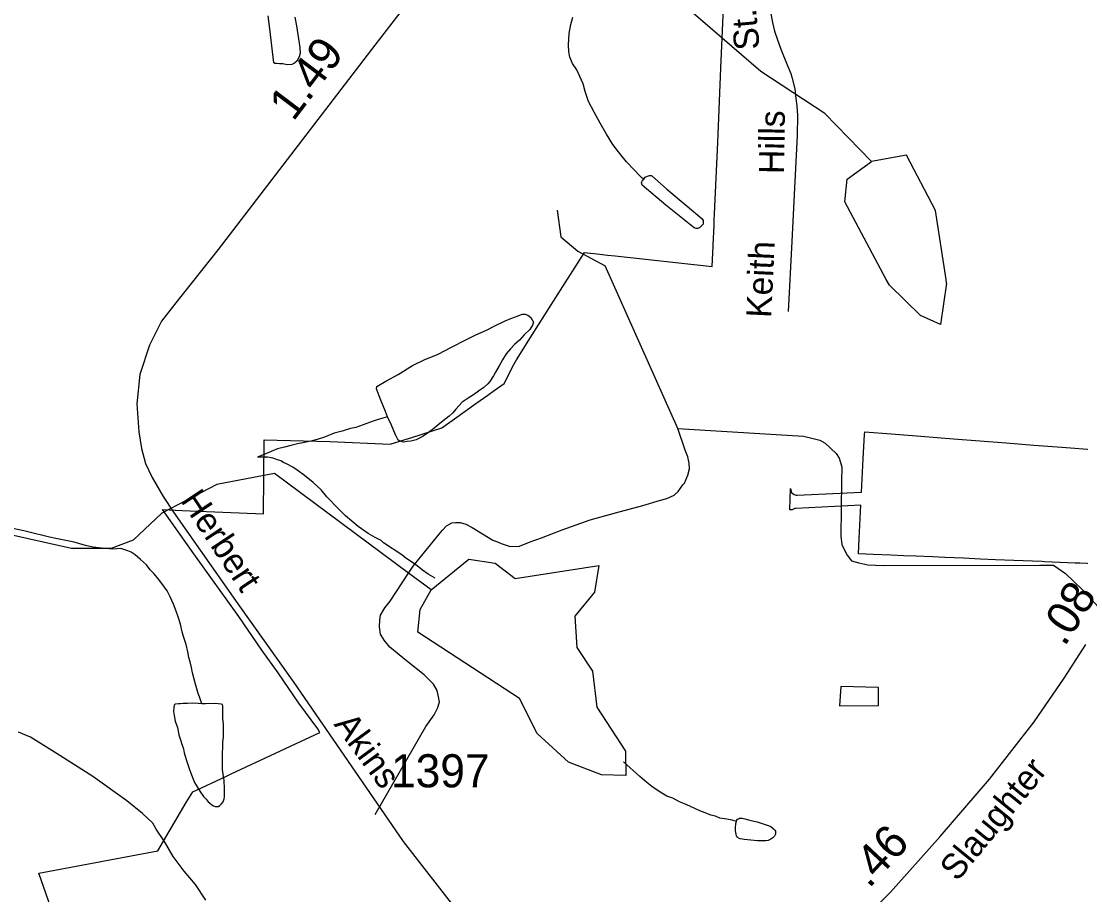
# Model space of a CAD drawing. Extents: x 2001466 to 2224147, y 644118 to 847247.
# Drawn here: x 2058287 to 2062288, y 680203 to 683500 of the extents above; entities that cross this region are included whole.
import ezdxf

# ---------------------------------------------------------------- set-up
doc = ezdxf.new("R2010")
doc.units = 0
for name, color, linetype in [('Exist Boundary Political City Limit New', 7, 'Continuous'), ('Exist Hydrographic Misc Water Feature', 7, 'Continuous'), ('Exist Road Non-System Type 51', 7, 'Continuous'), ('Exist Road Non-System Type 51 Label', 7, 'Continuous'), ('Exist Road Secondary Mileage Hundredths English Label', 7, 'Continuous'), ('Exist Road Secondary Type 51 Attributed', 7, 'Continuous'), ('Exist Road Secondary Type 51 Label', 7, 'Continuous'), ('Exist Road Secondary Type 51 Number Label', 7, 'Continuous'), ('Map Preparation Boundary City Limit Buffer Line', 7, 'Continuous')]:
    doc.layers.add(name, color=color, linetype=linetype)

msp = doc.modelspace()

# ---------------------------------------------------------------- linework, layer by layer
at = {"layer": 'Exist Boundary Political City Limit New'}
for points in [[(2058453.5, 680000), (2058353.2, 680284.1), (2058802.8, 680368.7), (2058909.6, 680551.6), (2058935.1, 680591.3), (2059059.1, 680650), (2059079.1, 680659.3), (2059414.8, 680815.9), (2059406.5, 680829.3), (2059335.6, 680926), (2059257.6, 681041), (2059195.1, 681126.8), (2059108.8, 681252.8), (2058938.4, 681490.1), (2058819.9, 681657), (2058894.9, 681653.8), (2059202, 681640.7), (2059204.4, 681919.9), (2059452.8, 681914.1), (2059679.9, 681903.6), (2059737.2, 681921.8), (2059761.2, 681929.3), (2059875.4, 681965.4), (2059922.6, 681999.1), (2060003.6, 682057), (2060048.4, 682088.9), (2060072.4, 682106.1), (2060110.1, 682133), (2060147.2, 682205.1), (2060156.4, 682222.8), (2060216.4, 682317.1), (2060288.2, 682430), (2060413.8, 682627), (2060471.5, 682620.6), (2060500.8, 682617.6), (2060530, 682614.4), (2060896, 682575.1), (2060899.2, 682651.2), (2060899.5, 682656.1), (2060902.8, 682729.5), (2060903.6, 682751), (2060904.6, 682772.7), (2060916.5, 683042.6), (2060928.9, 683323.6), (2060941.4, 683609.2)], [(2062423.1, 681448.3), (2062283.5, 681454.3), (2062266, 681455.1), (2062150.1, 681460), (2062139.9, 681460.4), (2062034.2, 681465), (2061965.6, 681467.9), (2061909.4, 681470.4), (2061845.2, 681473.2), (2061774.5, 681476.2), (2061728.8, 681478.2), (2061664.5, 681481), (2061618.9, 681482.9), (2061570.2, 681485.1), (2061503.9, 681488), (2061447.8, 681490.3), (2061450.8, 681548.2), (2061456, 681648.1), (2061457.2, 681673.1), (2061211.9, 681661), (2061208, 681660.5), (2061200.6, 681657.7), (2061197.4, 681655.4), (2061188.8, 681655.7), (2061191, 681737), (2061193.5, 681725), (2061195.6, 681721.5), (2061201.6, 681715.8), (2061205.1, 681713.7), (2061213, 681711.4), (2061217.1, 681711.3), (2061459.9, 681723.3), (2061461.1, 681748.1), (2061466.4, 681847.9), (2061471.2, 681940.3), (2061471.8, 681950.3), (2061571.5, 681942.5), (2061683.5, 681933.8), (2061806.5, 681924.2), (2061906.4, 681916.4), (2062006, 681908.7), (2062110.8, 681900.6), (2062215.4, 681892.5), (2062345, 681882.4)]]:
    msp.add_lwpolyline(points, dxfattribs=at)
at = {"layer": 'Exist Hydrographic Misc Water Feature'}
for p, q in [((2061564.7, 682503.5), (2061553.2, 682525.1)), ((2061780.7, 682512.2), (2061757.7, 682355.2)), ((2061780.7, 682512.2), (2061778.6, 682525.6)), ((2059834.7, 681354.2), (2059749.7, 681417.2))]:
    msp.add_line(p, q, dxfattribs=at)
for points in [[(2061079.9, 683310.6), (2060778.8, 683569.3), (2060553.8, 683826.5), (2060177.8, 684523.2), (2059809.9, 684989.9), (2059584.8, 685299.6), (2059442.9, 685414.1), (2059116.8, 685830.8), (2058824.8, 685813.8)], [(2059320.2, 683515.2), (2059326.4, 683483.4), (2059338.7, 683401.2), (2059340.5, 683379.4), (2059336.4, 683365.5), (2059328.2, 683349.3), (2059318.4, 683341.5), (2059308.3, 683337.3), (2059290.5, 683335.1), (2059274.7, 683339.1), (2059262.4, 683339), (2059252.6, 683341.3), (2059244.4, 683341.3), (2059240.5, 683343.1), (2059226.1, 683471), (2059220, 683521)], [(2060637.1, 682903.8), (2060630.9, 682908), (2060621.1, 682918), (2060601, 682939.7), (2060572.9, 682969.9), (2060550.8, 682995.6), (2060520.8, 683035.4), (2060496.6, 683073.6), (2060473, 683115.7), (2060450.7, 683157.6), (2060428.5, 683197.5), (2060416.4, 683235.4), (2060408.4, 683263.4), (2060396.6, 683291.2), (2060384.7, 683317.3), (2060368.3, 683341.2), (2060358.2, 683365.1), (2060354.3, 683385.2), (2060353.9, 683411.2), (2060356.4, 683453.4), (2060362.1, 683487.4), (2060370.1, 683515.4)], [(2061496.7, 682970.7), (2061321.7, 683151.5), (2061079.9, 683310.6)], [(2061778.6, 682525.6), (2061738.6, 682785.4), (2061629.7, 682994.3), (2061496.7, 682970.7)], [(2061553.2, 682525.1), (2061396.8, 682818.5), (2061404.8, 682903.7), (2061496.7, 682970.7)], [(2060637.1, 682903.8), (2060643, 682911.9), (2060651, 682915.9), (2060659, 682918), (2060662.9, 682918.2), (2060667, 682918), (2060725, 682866.1), (2060801.1, 682802.3), (2060857.5, 682754.4), (2060861.6, 682748.5), (2060861.4, 682742.5), (2060861.2, 682734.3), (2060855.3, 682728.4), (2060849.5, 682722.3), (2060841.1, 682718.3), (2060835.4, 682718.5), (2060827.6, 682720.5), (2060721.1, 682805.9), (2060631.3, 682882), (2060629.3, 682890), (2060633, 682900), (2060637.1, 682903.8)], [(2061757.7, 682355.2), (2061682.6, 682389.5), (2061564.7, 682503.5)], [(2059670.3, 682007.6), (2059662.1, 682027.5), (2059644.4, 682069.5), (2059628.4, 682113.3), (2059630.1, 682121.2), (2059664.1, 682141.6), (2059710, 682167.4), (2059764.2, 682201.4), (2059808.1, 682221.6), (2059861.8, 682243.8), (2059911.6, 682270), (2059966.1, 682297.8), (2060003.9, 682316), (2060043.5, 682333.9), (2060075.4, 682350.1), (2060111.7, 682368.2), (2060135.9, 682378.3), (2060163.4, 682388.3), (2060177.8, 682394.3), (2060189.7, 682394.5), (2060199.5, 682390.2), (2060211.4, 682382.3), (2060221.6, 682364.5), (2060218, 682352.5), (2060207.5, 682336.2), (2060186, 682316.3), (2060167.7, 682296.4), (2060149.7, 682280.1), (2060133.9, 682264.2), (2060117.9, 682244.4), (2060103.9, 682222.1), (2060092, 682200), (2060077.9, 682176.2), (2060070.1, 682161.9), (2060056.2, 682140.1), (2060048.2, 682132.1), (2060033.8, 682118), (2060014.1, 682103.9), (2059994.2, 682089.9), (2059974.1, 682078), (2059952.2, 682061.8), (2059928.4, 682035.8), (2059916.3, 682021.8), (2059902.4, 682009.7), (2059880.6, 681992), (2059860.5, 681975.9), (2059838.4, 681957.8), (2059820.8, 681945.9), (2059804.6, 681933.7), (2059792.7, 681927.8), (2059778.5, 681919.8), (2059758.6, 681915.5), (2059744.3, 681913.6), (2059730.3, 681911.7), (2059716.6, 681915.4), (2059710.4, 681919.6), (2059700.6, 681939.3), (2059684.4, 681975.4), (2059670.3, 682007.6)], [(2059670.3, 682007.6), (2059652.2, 682001.4), (2059630.5, 681995.4), (2059612.4, 681989.2), (2059578.6, 681977.3), (2059550.5, 681967.3), (2059530.6, 681963), (2059498.4, 681952.9), (2059468.7, 681944.9), (2059432.6, 681930.8), (2059404.7, 681920.9), (2059380.7, 681914.8), (2059350.8, 681908.8), (2059330.7, 681905), (2059304.4, 681898.8), (2059280.5, 681892.7), (2059254.4, 681886.5), (2059230.6, 681876.7), (2059206.4, 681866.6), (2059179, 681854.6)], [(2059849.7, 681398), (2059823.4, 681413.7), (2059801.5, 681428), (2059775.4, 681449.8), (2059739.4, 681473.5), (2059723.6, 681485.6), (2059655.1, 681531.7), (2059645.4, 681539.7), (2059623.1, 681551.6), (2059597.3, 681567.2), (2059559.1, 681593.3), (2059510.9, 681633.1), (2059485.1, 681659.3), (2059441, 681704.9), (2059418.9, 681731), (2059388.7, 681759.1), (2059356.9, 681785), (2059332.7, 681802.8), (2059312.9, 681816.8), (2059291.1, 681828.6), (2059276.8, 681834.8), (2059266.7, 681840.8), (2059250.7, 681846.5), (2059238.6, 681850.8), (2059230.8, 681852.8), (2059216.7, 681854.5), (2059179, 681854.6)], [(2059749.7, 681417.2), (2059242.7, 681792.8), (2059025.8, 681751.3), (2058817.7, 681644), (2058709.8, 681541.1), (2058626.7, 681510), (2058476.6, 681509.8), (2058042.8, 681607.2), (2057455.5, 681790.9)], [(2058663.2, 681509.7), (2058633.5, 681507.7), (2058589.6, 681511.5), (2058557.6, 681515.6), (2058529.6, 681521.4), (2058487.5, 681533.5), (2058461.7, 681539.5), (2058417.6, 681547.3), (2058393.4, 681553), (2058369.2, 681559.1), (2058337.4, 681567.2), (2058297.4, 681576.9), (2058249.5, 681587)], [(2058968.6, 680924.3), (2058960.2, 680950.3), (2058954.6, 680962.2), (2058944.4, 680998.2), (2058940.3, 681016.3), (2058934.3, 681040.3), (2058930, 681060.4), (2058924.5, 681082.3), (2058920.4, 681098.4), (2058916.3, 681120.1), (2058910.3, 681148.2), (2058900.1, 681178.1), (2058894.1, 681196), (2058888.2, 681224.1), (2058880, 681252.1), (2058871.8, 681274.1), (2058861.7, 681299.9), (2058849.8, 681328.1), (2058837.7, 681350.2), (2058817.7, 681378), (2058801.9, 681399.9), (2058787.9, 681415.8), (2058773.8, 681430.1), (2058759.6, 681448), (2058737.5, 681468), (2058717.6, 681485.6), (2058701.8, 681495.7), (2058689.5, 681501.6), (2058663.2, 681509.7)], [(2059834.7, 681354.2), (2059976.6, 681469.5), (2060076.7, 681454.3), (2060151.7, 681397), (2060467.7, 681446.4), (2060451.7, 681345), (2060376.7, 681254.6), (2060384.7, 681136.4), (2060443.7, 681046.6), (2060460.7, 680911.7), (2060568.6, 680745.5), (2060569.6, 680653.6), (2060477.8, 680655.4), (2060352.7, 680703.9), (2060235.6, 680811.3), (2060168.7, 680943.9), (2059784.7, 681194.5), (2059793.7, 681279.6), (2059834.7, 681354.2)], [(2061381.8, 680988.8), (2061376.1, 680916.7), (2061524.1, 680917), (2061523.9, 680985.1), (2061381.8, 680988.8)], [(2058968.6, 680924.3), (2058954.6, 680924.5), (2058934.5, 680926.2), (2058914.6, 680924.4), (2058898.4, 680924.5), (2058888.8, 680924.3), (2058880.6, 680924.3), (2058868.3, 680922.1), (2058864.8, 680918.2), (2058862.6, 680910), (2058862.4, 680894.2), (2058864.8, 680880.1), (2058868.7, 680858), (2058876.7, 680834), (2058882.7, 680806.4), (2058889, 680788.3), (2058894.5, 680768), (2058899.1, 680754.4), (2058902.7, 680738.4), (2058910.9, 680710.4), (2058921.2, 680680.1), (2058927.1, 680662.1), (2058941.1, 680626.4), (2058951.1, 680610.2), (2058960.8, 680594.6), (2058975.3, 680574.5), (2058985.2, 680564.5), (2058993.2, 680554.3), (2058997.3, 680550.5), (2059006.9, 680542.5), (2059013.3, 680538.7), (2059019.2, 680536.6), (2059022.9, 680536.4), (2059031.1, 680536.4), (2059037.3, 680540.4), (2059043.4, 680546.3), (2059048.9, 680554.4), (2059053.3, 680564.7), (2059054.9, 680572.6), (2059055.1, 680586.7), (2059055.1, 680604.6), (2059052.8, 680634.6), (2059048.9, 680658.7), (2059046.7, 680676.4), (2059046.9, 680710.5), (2059047.1, 680734.4), (2059048.7, 680762.5), (2059048.7, 680780.4), (2059050.6, 680798.3), (2059050.4, 680818.6), (2059050.6, 680826.7), (2059050.4, 680846.6), (2059048.5, 680868.4), (2059048.5, 680886.7), (2059048.5, 680906.6), (2059048.5, 680916.3), (2059046.7, 680920.6), (2059042.4, 680922.5), (2059030.3, 680924.3), (2059020.4, 680924.6), (2058982.7, 680924.2), (2058968.6, 680924.3)], [(2060987.1, 680480), (2060970.7, 680484.1), (2060951, 680487.9), (2060924.8, 680491.9), (2060908.8, 680500), (2060890.7, 680503.9), (2060869.2, 680512.1), (2060848.9, 680520), (2060832.7, 680527.8), (2060811, 680537.9), (2060791.1, 680545.8), (2060772.8, 680553.9), (2060746.6, 680567.6), (2060725, 680575.7), (2060699, 680589.8), (2060668.5, 680611.5), (2060648.6, 680627.4), (2060622.5, 680649.3), (2060560.4, 680705.3)], [(2060987.1, 680480), (2060988.9, 680484.2), (2060991, 680488.4), (2060994.7, 680490.2), (2060998.8, 680492), (2061008.6, 680492.1), (2061018.9, 680490.2), (2061032.6, 680486.1), (2061048.6, 680482.5), (2061065, 680478.4), (2061084.9, 680472.5), (2061106.9, 680464.3), (2061116.9, 680460.4), (2061126.9, 680452.3), (2061132.9, 680446.6), (2061135.1, 680442.6), (2061135.1, 680432.4), (2061130.8, 680424.6), (2061125.1, 680418.5), (2061116.9, 680412.5), (2061106.9, 680408.3), (2061098.9, 680406.3), (2061089.2, 680406.5), (2061067.1, 680406.2), (2061028.9, 680410.4), (2061017, 680412.2), (2061001.3, 680414.2), (2060995.1, 680416.3), (2060991.2, 680420.2), (2060987.1, 680426.1), (2060983.2, 680444.1), (2060983.2, 680454.3), (2060984.8, 680472.3), (2060987.1, 680480)]]:
    msp.add_lwpolyline(points, dxfattribs=at)
at = {"layer": 'Exist Road Non-System Type 51'}
msp.add_line((2060765.6, 681963.3), (2060491.7, 682577.4), dxfattribs=at)
for points in [[(2061118, 683610.8), (2061114.4, 683558.1), (2061115.9, 683534.1), (2061123.7, 683495.6), (2061130.8, 683462.9), (2061140.7, 683434.4), (2061155, 683394.6), (2061179.1, 683336.2), (2061193.3, 683303.5)], [(2061193.3, 683303.5), (2061197.1, 683288.8), (2061208.2, 683244.6), (2061211.5, 683208.5), (2061214.9, 683180.5), (2061218.2, 683144.4), (2061216.6, 683068.4), (2061204, 682821.2), (2061196.9, 682668.9), (2061182.7, 682404.3)], [(2060310.4, 682786.9), (2060324.4, 682687), (2060388.3, 682632.2), (2060491.7, 682577.4)], [(2059749.7, 681417.2), (2059767, 681443.6), (2059865.5, 681563.6), (2059877.8, 681579.4), (2059892.1, 681595.1), (2059912.3, 681606.7), (2059926.4, 681608.4), (2059944.4, 681608), (2059966.2, 681601.6), (2059990, 681589.1), (2060067, 681541.5), (2060084.9, 681535.2), (2060098.8, 681528.9), (2060110.7, 681524.6), (2060132.5, 681518.2), (2060168.6, 681519.4), (2060208.9, 681534.6), (2060251.2, 681549.8), (2060329.8, 681580.2), (2060434.6, 681618), (2060531.1, 681644.1), (2060633.7, 681672), (2060700.1, 681692.7), (2060724.2, 681698.2), (2060752.5, 681711.6), (2060766.8, 681725.3), (2060785.3, 681750.9), (2060791.4, 681756.8), (2060804, 681786.5), (2060810.5, 681810.4), (2060808.9, 681832.4), (2060803.4, 681856.6), (2060793.9, 681880.8), (2060765.6, 681963.3)], [(2060765.6, 681963.3), (2061241, 681933.7), (2061276.8, 681924.9), (2061302.7, 681918.4), (2061322.5, 681908), (2061363.7, 681869.2), (2061375.3, 681850.9), (2061384.7, 681818.8), (2061383.5, 681762.8), (2061381.3, 681556.8), (2061384.7, 681524.8), (2061392.3, 681508.6), (2061405.8, 681484.3), (2061421.4, 681464), (2061449.3, 681455.4), (2061483.1, 681448.8), (2061541.1, 681445.6), (2062133.4, 681446.9), (2062184.6, 681446.9), (2062230.1, 681415.7), (2062292.6, 681355.9), (2062355.1, 681287.7)], [(2059623.3, 680505.6), (2059814.7, 680838.6), (2059845.6, 680882), (2059860.1, 680909.7), (2059866.6, 680931.6), (2059863, 680949.7), (2059857.5, 680973.8), (2059843.9, 680998), (2059808.7, 681032.8), (2059741.7, 681086.1), (2059678.8, 681137.4), (2059657.3, 681163.8), (2059643.8, 681186.1), (2059640.3, 681214.2), (2059640.9, 681240.2), (2059643.2, 681258.1), (2059659.8, 681285.8), (2059680.3, 681311.4), (2059749.7, 681417.2)], [(2058983.6, 680183), (2058944.8, 680241.8), (2058901.8, 680292.7), (2058861, 680347.5), (2058828.1, 680404.2), (2058797.1, 680450.8), (2058783.5, 680473.1), (2058744.3, 680509.9), (2058685.2, 680557.1), (2058557.1, 680649.7), (2058432.7, 680728.2), (2058322.1, 680798.4), (2058276.5, 680817.4)]]:
    msp.add_lwpolyline(points, dxfattribs=at)
at = {"layer": 'Exist Road Secondary Type 51 Attributed'}
for points in [[(2059771.3, 683604.7), (2059621.9, 683410.2), (2059030.3, 682639), (2058865.3, 682431.3), (2058817, 682368.7), (2058771.5, 682277.6), (2058734.5, 682166.6), (2058723.1, 682055.7), (2058731.7, 681950.4), (2058740.6, 681888), (2058756.1, 681830.6), (2058780.9, 681777.8), (2058822.8, 681706.5), (2058861.6, 681647.5), (2059105.4, 681301.5), (2059316.9, 681004.3), (2059532.2, 680689.3), (2059729.5, 680403.8), (2059936.2, 680137)], [(2060508, 679534.3), (2060552.2, 679608.9), (2060600.6, 679656.5), (2060652.2, 679690.1), (2060798.9, 679760.6), (2061116.9, 679901.7), (2061264.5, 679972.2), (2061371, 680032.9), (2061466.1, 680108.3), (2061569.4, 680213.3), (2061756.2, 680423.2), (2061943.1, 680639.7), (2062112, 680856.2), (2062225, 681020.9), (2062307, 681148)]]:
    msp.add_lwpolyline(points, dxfattribs=at)
at = {"layer": 'Map Preparation Boundary City Limit Buffer Line'}
for points in [[(2058453.5, 680000), (2058353.2, 680284.1), (2058802.8, 680368.7), (2058909.6, 680551.6), (2058935.1, 680591.3), (2059059.1, 680650), (2059079.1, 680659.3), (2059414.8, 680815.9), (2059406.5, 680829.3), (2059335.6, 680926), (2059257.6, 681041), (2059195.1, 681126.8), (2059108.8, 681252.8), (2058938.4, 681490.1), (2058819.9, 681657), (2058894.9, 681653.8), (2059202, 681640.7), (2059204.4, 681919.9), (2059452.8, 681914.1), (2059679.9, 681903.6), (2059737.2, 681921.8), (2059761.2, 681929.3), (2059875.4, 681965.4), (2059922.6, 681999.1), (2060003.6, 682057), (2060048.4, 682088.9), (2060072.4, 682106.1), (2060110.1, 682133), (2060147.2, 682205.1), (2060156.4, 682222.8), (2060216.4, 682317.1), (2060288.2, 682430), (2060413.8, 682627), (2060471.5, 682620.6), (2060500.8, 682617.6), (2060530, 682614.4), (2060896, 682575.1), (2060899.2, 682651.2), (2060899.5, 682656.1), (2060902.8, 682729.5), (2060903.6, 682751), (2060904.6, 682772.7), (2060916.5, 683042.6), (2060928.9, 683323.6), (2060941.4, 683609.2)], [(2062423.1, 681448.3), (2062283.5, 681454.3), (2062266, 681455.1), (2062150.1, 681460), (2062139.9, 681460.4), (2062034.2, 681465), (2061965.6, 681467.9), (2061909.4, 681470.4), (2061845.2, 681473.2), (2061774.5, 681476.2), (2061728.8, 681478.2), (2061664.5, 681481), (2061618.9, 681482.9), (2061570.2, 681485.1), (2061503.9, 681488), (2061447.8, 681490.3), (2061450.8, 681548.2), (2061456, 681648.1), (2061457.2, 681673.1), (2061211.9, 681661), (2061208, 681660.5), (2061200.6, 681657.7), (2061197.4, 681655.4), (2061188.8, 681655.7), (2061191, 681737), (2061193.5, 681725), (2061195.6, 681721.5), (2061201.6, 681715.8), (2061205.1, 681713.7), (2061213, 681711.4), (2061217.1, 681711.3), (2061459.9, 681723.3), (2061461.1, 681748.1), (2061466.4, 681847.9), (2061471.2, 681940.3), (2061471.8, 681950.3), (2061571.5, 681942.5), (2061683.5, 681933.8), (2061806.5, 681924.2), (2061906.4, 681916.4), (2062006, 681908.7), (2062110.8, 681900.6), (2062215.4, 681892.5), (2062345, 681882.4)]]:
    msp.add_lwpolyline(points, dxfattribs=at)

# ---------------------------------------------------------------- texts
at = {"layer": 'Exist Road Non-System Type 51 Label'}
for s, rotation, p in [(' St.', 95.2551, (2061078.6, 683360.5)), ('Hills', 89.2673, (2061167.2, 682923.1)), ('Keith', 87.3657, (2061118.6, 682379.2))]:
    msp.add_text(s, height=95, rotation=rotation, dxfattribs=at).set_placement(p)
at = {"layer": 'Exist Road Secondary Mileage Hundredths English Label'}
for s, rotation, p in [('1.49', 52.9351, (2059314.2, 683118.9)), ('.08', 57.3989, (2062225.9, 681136.5)), ('.46', 46.9461, (2061487.4, 680224.2))]:
    msp.add_text(s, height=125, rotation=rotation, dxfattribs=at).set_placement(p)
at = {"layer": 'Exist Road Secondary Type 51 Label'}
for s, rotation, p in [('Herbert', 303.5864, (2058885.7, 681691.9)), ('Akins', 306.3103, (2059465, 680845.9)), ('Slaughter', 50.8079, (2061821.3, 680249.8))]:
    msp.add_text(s, height=95, rotation=rotation, dxfattribs=at).set_placement(p)
at = {"layer": 'Exist Road Secondary Type 51 Number Label'}
msp.add_text('1397', height=125, dxfattribs=at).set_placement((2059683.3, 680608.5))

doc.saveas('drawing.dxf')
